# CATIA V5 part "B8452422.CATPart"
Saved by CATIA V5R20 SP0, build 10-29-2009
Part number: B8452422
Revision: 2
Definition: design
Nomenclature: B8452422
Source: made
Description: NOT SPECIFIED
Bounding box of the stored display mesh (mm): x -20.5 to 20.5, y -20.5 to 20.5, z -17 to 22
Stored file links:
  C:\Users\Utente\Desktop\3D files B845\B8452422.CATPart
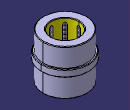
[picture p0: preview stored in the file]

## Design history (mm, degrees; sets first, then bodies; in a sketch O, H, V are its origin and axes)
Body1 "MANIFOLD_SOLID_BREP #38" (main body)
  Solid1: solid without history
Body2 "MANIFOLD_SOLID_BREP #76"
  Solid2: solid without history
Body3 "MANIFOLD_SOLID_BREP #114"
  Solid3: solid without history
Body4 "MANIFOLD_SOLID_BREP #152"
  Solid4: solid without history
Body5 "MANIFOLD_SOLID_BREP #190"
  Solid5: solid without history
Body6 "MANIFOLD_SOLID_BREP #2254"
  Solid6: solid without history
Body7 "MANIFOLD_SOLID_BREP #2292"
  Solid7: solid without history
Body8 "MANIFOLD_SOLID_BREP #2330"
  Solid8: solid without history
Body9 "MANIFOLD_SOLID_BREP #2368"
  Solid9: solid without history
Body10 "MANIFOLD_SOLID_BREP #2406"
  Solid10: solid without history
Body11 "MANIFOLD_SOLID_BREP #2444"
  Solid11: solid without history
Body12 "MANIFOLD_SOLID_BREP #2482"
  Solid12: solid without history
Body13 "MANIFOLD_SOLID_BREP #2520"
  Solid13: solid without history
Body14 "MANIFOLD_SOLID_BREP #2558"
  Solid14: solid without history
Body15 "MANIFOLD_SOLID_BREP #2596"
  Solid15: solid without history
Body16 "MANIFOLD_SOLID_BREP #2634"
  Solid16: solid without history
Body17 "MANIFOLD_SOLID_BREP #2672"
  Solid17: solid without history
Body18 "MANIFOLD_SOLID_BREP #2710"
  Solid18: solid without history
Body19 "MANIFOLD_SOLID_BREP #2748"
  Solid19: solid without history
Body20 "MANIFOLD_SOLID_BREP #2786"
  Solid20: solid without history
Body21 "MANIFOLD_SOLID_BREP #2824"
  Solid21: solid without history
Body22 "MANIFOLD_SOLID_BREP #2862"
  Solid22: solid without history
Body23 "MANIFOLD_SOLID_BREP #2900"
  Solid23: solid without history
Body24 "MANIFOLD_SOLID_BREP #2938"
  Solid24: solid without history
Body25 "MANIFOLD_SOLID_BREP #2976"
  Solid25: solid without history
Body26 "MANIFOLD_SOLID_BREP #3014"
  Solid26: solid without history
Body27 "MANIFOLD_SOLID_BREP #3052"
  Solid27: solid without history
Body28 "MANIFOLD_SOLID_BREP #3090"
  Solid28: solid without history
Body29 "MANIFOLD_SOLID_BREP #3128"
  Solid29: solid without history
Body30 "MANIFOLD_SOLID_BREP #3166"
  Solid30: solid without history
Body31 "MANIFOLD_SOLID_BREP #3204"
  Solid31: solid without history
Body32 "MANIFOLD_SOLID_BREP #3242"
  Solid32: solid without history
Body33 "MANIFOLD_SOLID_BREP #3280"
  Solid33: solid without history
Body34 "MANIFOLD_SOLID_BREP #3318"
  Solid34: solid without history
Body35 "MANIFOLD_SOLID_BREP #3356"
  Solid35: solid without history
Body36 "MANIFOLD_SOLID_BREP #3394"
  Solid36: solid without history
Body37 "MANIFOLD_SOLID_BREP #3432"
  Solid37: solid without history
Body38 "MANIFOLD_SOLID_BREP #3470"
  Solid38: solid without history
Body39 "MANIFOLD_SOLID_BREP #3508"
  Solid39: solid without history
Body40 "MANIFOLD_SOLID_BREP #3546"
  Solid40: solid without history
Body41 "MANIFOLD_SOLID_BREP #3584"
  Solid41: solid without history
Body42 "MANIFOLD_SOLID_BREP #3622"
  Solid42: solid without history
Body43 "MANIFOLD_SOLID_BREP #3660"
  Solid43: solid without history
Body44 "MANIFOLD_SOLID_BREP #3698"
  Solid44: solid without history
Body45 "MANIFOLD_SOLID_BREP #3736"
  Solid45: solid without history
Body46 "MANIFOLD_SOLID_BREP #3774"
  Solid46: solid without history
Body47 "MANIFOLD_SOLID_BREP #3812"
  Solid47: solid without history
Body48 "MANIFOLD_SOLID_BREP #3850"
  Solid48: solid without history
Body49 "MANIFOLD_SOLID_BREP #3888"
  Solid49: solid without history
Body50 "MANIFOLD_SOLID_BREP #3926"
  Solid50: solid without history
Body51 "MANIFOLD_SOLID_BREP #3964"
  Solid51: solid without history
Body52 "MANIFOLD_SOLID_BREP #4002"
  Solid52: solid without history
Body53 "MANIFOLD_SOLID_BREP #4040"
  Solid53: solid without history
Body54 "MANIFOLD_SOLID_BREP #4078"
  Solid54: solid without history
Body55 "MANIFOLD_SOLID_BREP #4116"
  Solid55: solid without history
Body56 "MANIFOLD_SOLID_BREP #4154"
  Solid56: solid without history
Body57 "MANIFOLD_SOLID_BREP #4192"
  Solid57: solid without history
Body58 "MANIFOLD_SOLID_BREP #4230"
  Solid58: solid without history
Body59 "MANIFOLD_SOLID_BREP #4268"
  Solid59: solid without history
Body60 "MANIFOLD_SOLID_BREP #4306"
  Solid60: solid without history
Body61 "MANIFOLD_SOLID_BREP #4344"
  Solid61: solid without history
Body62 "MANIFOLD_SOLID_BREP #4382"
  Solid62: solid without history
Body63 "MANIFOLD_SOLID_BREP #4420"
  Solid63: solid without history
Body64 "MANIFOLD_SOLID_BREP #4458"
  Solid64: solid without history
Body65 "MANIFOLD_SOLID_BREP #4496"
  Solid65: solid without history
Body66 "MANIFOLD_SOLID_BREP #4534"
  Solid66: solid without history
Body67 "MANIFOLD_SOLID_BREP #4572"
  Solid67: solid without history
Body68 "MANIFOLD_SOLID_BREP #4610"
  Solid68: solid without history
Body69 "MANIFOLD_SOLID_BREP #4648"
  Solid69: solid without history
Body70 "MANIFOLD_SOLID_BREP #4686"
  Solid70: solid without history
Body71 "MANIFOLD_SOLID_BREP #4724"
  Solid71: solid without history
Body72 "MANIFOLD_SOLID_BREP #4762"
  Solid72: solid without history
Body73 "MANIFOLD_SOLID_BREP #4800"
  Solid73: solid without history
Body74 "MANIFOLD_SOLID_BREP #4838"
  Solid74: solid without history
Body75 "MANIFOLD_SOLID_BREP #4876"
  Solid75: solid without history
Body76 "MANIFOLD_SOLID_BREP #4914"
  Solid76: solid without history
Body77 "MANIFOLD_SOLID_BREP #4952"
  Solid77: solid without history
Body78 "MANIFOLD_SOLID_BREP #4990"
  Solid78: solid without history
Body79 "MANIFOLD_SOLID_BREP #5028"
  Solid79: solid without history
Body80 "MANIFOLD_SOLID_BREP #5066"
  Solid80: solid without history
Body81 "MANIFOLD_SOLID_BREP #5104"
  Solid81: solid without history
